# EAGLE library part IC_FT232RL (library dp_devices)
USB to serial UART interface
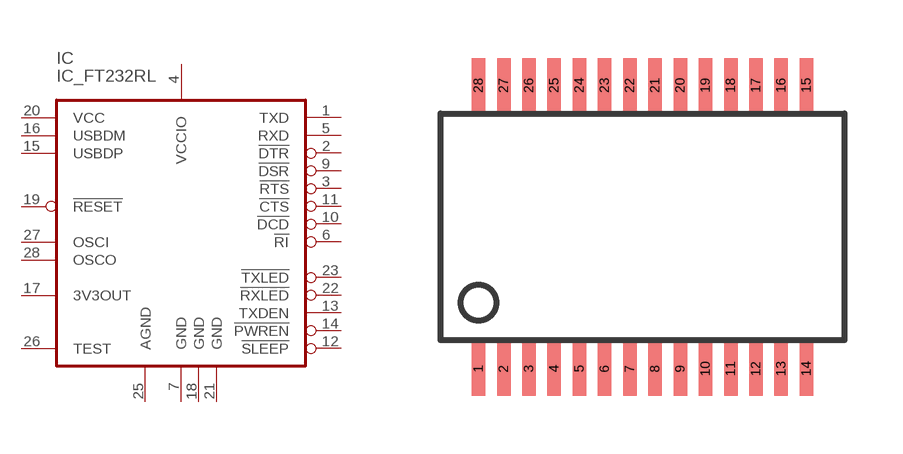
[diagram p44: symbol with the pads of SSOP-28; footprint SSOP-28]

Designator prefix IC

## IC_FT232RL  [SSOP-28]
1  TXD
2  !DTR
3  !RTS
4  VCCIO
5  RXD
6  !RI
7  GND
9  !DSR
10  !DCD
11  !CTS
12  !SLEEP
13  TXDEN
14  !PWREN
15  USBDP
16  USBDM
17  3V3OUT
18  GND
19  !RESET
20  VCC
21  GND
22  !RXLED
23  !TXLED
25  AGND
26  TEST
27  OSCI
28  OSCO

## Footprint SSOP-28 (pad centres in mm)
SSOP28
smd 0.348 x 1.397: 1 -4.225,-3.656; 2 -3.575,-3.656; 3 -2.925,-3.656; 4 -2.275,-3.656; 5 -1.625,-3.656; 6 -0.975,-3.656; 7 -0.325,-3.656; 8 0.325,-3.656; 9 0.975,-3.656; 10 1.625,-3.656; 11 2.275,-3.656; 12 2.925,-3.656; 13 3.575,-3.656; 14 4.225,-3.656; 15 4.225,3.656; 16 3.575,3.656; 17 2.925,3.656; 18 2.275,3.656; 19 1.625,3.656; 20 0.975,3.656; 21 0.325,3.656; 22 -0.325,3.656; 23 -0.975,3.656; 24 -1.625,3.656; 25 -2.275,3.656; 26 -2.925,3.656; 27 -3.575,3.656; 28 -4.225,3.656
